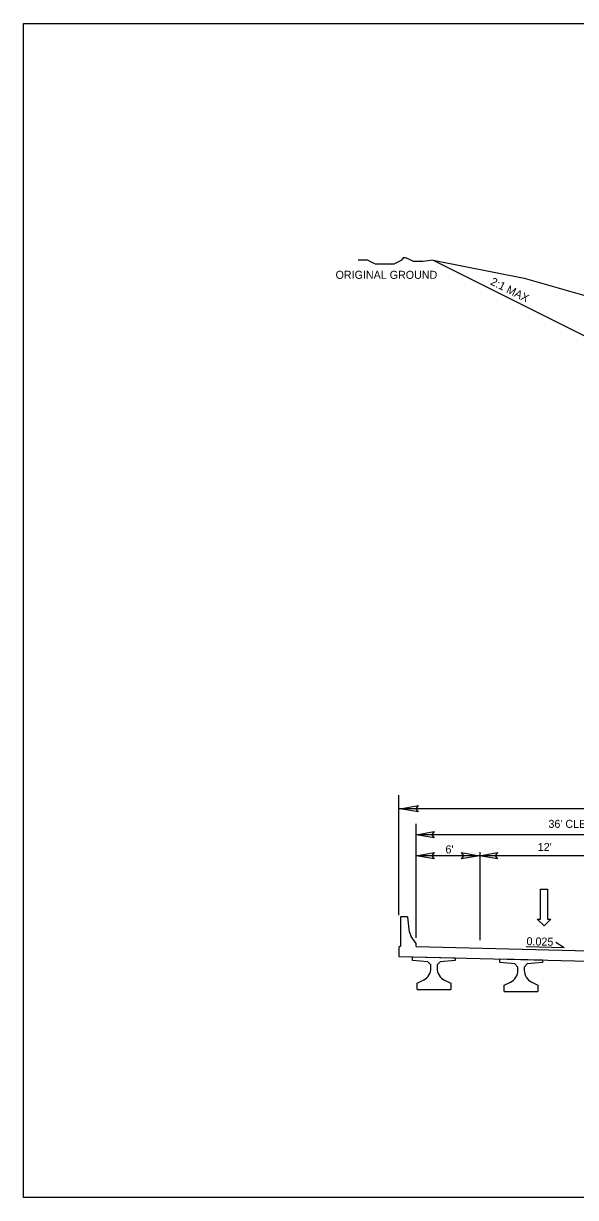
# Model space of a CAD drawing. Extents: x 1548135 to 1549339, y 868664 to 869085.
# Drawn here: x 1548135 to 1548186.8, y 868664.3 to 868774.3 of the extents above; entities that cross this region are included whole.
import ezdxf

# ---------------------------------------------------------------- set-up
doc = ezdxf.new("R2010")
doc.units = 0
for name, color, linetype in [('Default', 7, 'Continuous'), ('P_RDY_TC_Pvmt_Asphalt_Base_Course', 7, 'Continuous'), ('Sheet_Data_Field_CELL', 7, 'Continuous'), ('Typical Bridge Rail CELL', 7, 'Continuous'), ('Typical Grade Point Symbol CELL', 7, 'Continuous'), ('Typical Hinge Slope Interstate CELL', 7, 'Continuous'), ('Typical Pavement Slope Information CELL', 7, 'Continuous'), ('Typical Shoulder Slope CELL', 7, 'Continuous'), ('Typical Shoulder Slope Information CELL', 7, 'Continuous'), ('Typical Text ID Circle CELL', 7, 'Continuous')]:
    doc.layers.add(name, color=color, linetype=linetype)

msp = doc.modelspace()

# ---------------------------------------------------------------- linework, layer by layer
at = {"layer": 'Default'}
msp.add_lwpolyline([(1548135.05, 868774.32), (1548305.05, 868774.32), (1548305.05, 868664.32), (1548135.05, 868664.32)], close=True, dxfattribs=at)
at = {"layer": 'P_RDY_TC_Pvmt_Asphalt_Base_Course'}
for points in [[(1548172.04, 868700.46), (1548170.35, 868700.75), (1548172.05, 868701.05), (1548171.83, 868700.75)], [(1548173.54, 868698.03), (1548171.85, 868698.32), (1548173.55, 868698.62), (1548173.33, 868698.32)], [(1548173.54, 868696.06), (1548171.85, 868696.35), (1548173.55, 868696.65), (1548173.33, 868696.35)], [(1548176.11, 868696.64), (1548177.79, 868696.35), (1548176.1, 868696.05), (1548176.31, 868696.35)], [(1548179.48, 868696.06), (1548177.79, 868696.35), (1548179.49, 868696.65), (1548179.27, 868696.35)]]:
    msp.add_lwpolyline(points, close=True, dxfattribs=at)
at = {"layer": 'Sheet_Data_Field_CELL'}
msp.add_line((1548173.45, 868752.14), (1548189.05, 868744.34), dxfattribs=at)
msp.add_lwpolyline([(1548173.45, 868752.14), (1548172.47, 868752.01), (1548172.22, 868752.01), (1548171.85, 868752.01), (1548171.6, 868752.01), (1548171.36, 868752.14), (1548171.11, 868752.26), (1548170.86, 868752.38), (1548170.62, 868752.38), (1548170.49, 868752.14), (1548170.25, 868752.01), (1548170, 868751.89), (1548169.75, 868751.77), (1548169.51, 868751.77), (1548169.26, 868751.77), (1548169.02, 868751.77), (1548168.77, 868751.77), (1548168.52, 868751.77), (1548168.28, 868751.77), (1548168.03, 868751.77), (1548167.78, 868751.89), (1548167.54, 868752.01), (1548167.29, 868752.14), (1548166.92, 868752.14), (1548166.67, 868752.14), (1548166.43, 868752.14)], dxfattribs=at)
at = {"layer": 'Typical Bridge Rail CELL'}
for p, q in [((1548171.52, 868686.54), (1548171.52, 868686.88)), ((1548171.52, 868686.88), (1548175.52, 868686.78)), ((1548172.94, 868686.41), (1548171.52, 868686.54)), ((1548175.52, 868686.54), (1548174.1, 868686.41)), ((1548175.52, 868686.78), (1548175.52, 868686.54)), ((1548179.69, 868686.33), (1548179.69, 868686.68)), ((1548179.69, 868686.68), (1548183.69, 868686.58)), ((1548183.69, 868686.58), (1548183.69, 868686.33)), ((1548173.23, 868686.12), (1548172.94, 868686.41)), ((1548173.23, 868685.82), (1548173.23, 868686.12)), ((1548174.1, 868686.41), (1548173.81, 868686.12)), ((1548173.81, 868686.12), (1548173.81, 868685.82)), ((1548181.1, 868686.21), (1548179.69, 868686.33)), ((1548181.39, 868685.92), (1548181.1, 868686.21)), ((1548181.39, 868685.62), (1548181.39, 868685.92)), ((1548182.27, 868686.21), (1548181.98, 868685.92)), ((1548181.98, 868685.92), (1548181.98, 868685.62)), ((1548183.69, 868686.33), (1548182.27, 868686.21)), ((1548171.94, 868684.41), (1548172.52, 868684.7)), ((1548171.94, 868683.83), (1548171.94, 868684.41)), ((1548174.52, 868684.7), (1548175.1, 868684.41)), ((1548175.1, 868684.41), (1548175.1, 868683.83)), ((1548180.1, 868684.21), (1548180.69, 868684.49)), ((1548182.68, 868684.49), (1548183.27, 868684.21)), ((1548171.94, 868683.83), (1548175.1, 868683.83)), ((1548180.1, 868683.63), (1548180.1, 868684.21)), ((1548180.1, 868683.63), (1548183.27, 868683.63)), ((1548183.27, 868684.21), (1548183.27, 868683.63))]:
    msp.add_line(p, q, dxfattribs=at)
for centre, start, end in [((1548171.98, 868685.82), 295.821, 0), ((1548175.06, 868685.82), 180, 244.179), ((1548180.14, 868685.62), 295.821, 0), ((1548183.23, 868685.62), 180, 244.179)]:
    msp.add_arc(centre, 1.25, start, end, dxfattribs=at)
at = {"layer": 'Typical Grade Point Symbol CELL'}
for p, q in [((1548170.23, 868690.79), (1548170.23, 868702.02)), ((1548189.85, 868700.75), (1548170.23, 868700.75)), ((1548171.85, 868688.67), (1548171.85, 868699.35)), ((1548189.85, 868698.32), (1548171.85, 868698.32)), ((1548177.85, 868688.43), (1548177.85, 868696.68)), ((1548189.85, 868696.35), (1548171.85, 868696.35)), ((1548176.85, 868696.35), (1548174.85, 868696.35))]:
    msp.add_line(p, q, dxfattribs=at)
at = {"layer": 'Typical Hinge Slope Interstate CELL'}
msp.add_lwpolyline([(1548173.45, 868752.14), (1548181.96, 868750.47), (1548190.72, 868747.96), (1548198.89, 868746.19), (1548201.53, 868745.5), (1548206.62, 868743.75), (1548213.13, 868743.34), (1548217.71, 868742.31), (1548225.3, 868741.97), (1548231.61, 868741.94), (1548235.59, 868741.51), (1548243.7, 868741.08)], dxfattribs=at)
at = {"layer": 'Typical Pavement Slope Information CELL'}
for q in [(1548182.15, 868687.82), (1548184.94, 868688.21)]:
    msp.add_line((1548185.72, 868687.73), q, dxfattribs=at)
at = {"layer": 'Typical Shoulder Slope Information CELL'}
for p, q in [((1548183.5, 868690.4), (1548183.5, 868693.2)), ((1548183.5, 868693.2), (1548184.16, 868693.2)), ((1548184.16, 868693.2), (1548184.16, 868690.4)), ((1548183.84, 868689.77), (1548183.2, 868690.4)), ((1548183.2, 868690.4), (1548183.5, 868690.4)), ((1548184.46, 868690.4), (1548183.84, 868689.77)), ((1548184.16, 868690.4), (1548184.46, 868690.4))]:
    msp.add_line(p, q, dxfattribs=at)
at = {"layer": 'Typical Text ID Circle CELL'}
for p, q in [((1548170.41, 868690.63), (1548170.38, 868690.6)), ((1548170.38, 868690.6), (1548170.38, 868687.85)), ((1548171.04, 868690.63), (1548170.41, 868690.63)), ((1548171.07, 868690.59), (1548171.04, 868690.63)), ((1548171.22, 868689.2), (1548171.07, 868690.59)), ((1548171.85, 868688.11), (1548171.37, 868688.79)), ((1548170.31, 868687.85), (1548170.24, 868687.78)), ((1548170.24, 868687.78), (1548170.24, 868687.33)), ((1548170.38, 868687.85), (1548170.31, 868687.85)), ((1548171.85, 868687.85), (1548171.85, 868688.11)), ((1548171.85, 868687.85), (1548207.85, 868686.95)), ((1548170.24, 868687.33), (1548170.24, 868686.91)), ((1548170.24, 868686.91), (1548209.46, 868685.93))]:
    msp.add_line(p, q, dxfattribs=at)
msp.add_arc((1548172.09, 868689.29), 0.869, 186.0111, 214.9913, dxfattribs=at)

# ---------------------------------------------------------------- texts
at = {"layer": 'Sheet_Data_Field_CELL'}
msp.add_text('ORIGINAL GROUND', height=0.75, dxfattribs=at).set_placement((1548164.3, 868750.4))
msp.add_text('2:1 MAX', height=0.75, rotation=333.4349, dxfattribs=at).set_placement((1548178.74, 868749.9))
at = {"layer": 'Typical Hinge Slope Interstate CELL'}
msp.add_text("36' CLEAR ROADWAY", height=0.75, dxfattribs=at).set_placement((1548184.25, 868698.96))
at = {"layer": 'Typical Pavement Slope Information CELL'}
msp.add_text('0.025', height=0.75, rotation=358.568, dxfattribs=at).set_placement((1548182.19, 868687.97))
at = {"layer": 'Typical Shoulder Slope CELL'}
for s, p in [("12'", (1548183.25, 868696.79)), ("6'", (1548174.6, 868696.57))]:
    msp.add_text(s, height=0.75, dxfattribs=at).set_placement(p)

doc.saveas('drawing.dxf')
